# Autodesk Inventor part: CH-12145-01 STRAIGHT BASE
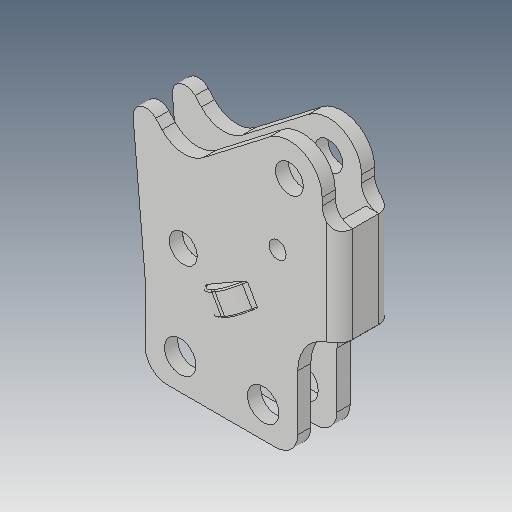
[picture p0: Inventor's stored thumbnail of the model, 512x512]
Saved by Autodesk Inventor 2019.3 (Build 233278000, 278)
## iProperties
Created: 2012-09
Part Number: CH-12145-01 STRAIGHT BASE
Material: Ogólny
Document SubType Name: Modeling
Designer: CADENGINEERING4
Density: 1 g/cm^3
Appearance: Domyślna
Author: CADENGINEERING4
Revision Number: ÈÎºÎ
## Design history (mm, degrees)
feature "ÇÐ³ý-À­Éì5"
node "Bryła1"
